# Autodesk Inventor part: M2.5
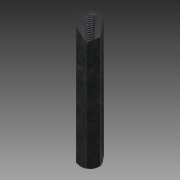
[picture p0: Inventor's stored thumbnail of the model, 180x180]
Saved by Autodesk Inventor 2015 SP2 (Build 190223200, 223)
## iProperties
Created: 2012-08
Part Number: M2.5
Material: Stahl
Document SubType Name: Modeling
Designer: rYan
Density: 7.85 g/cm^3
Mass: 3.36246 g
Surface Area: 5.74911 cm^2
Volume: 0.428339 cm^3
Appearance: Platte
Author: rYan
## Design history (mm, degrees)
derived "Abstandsbolzen Typ A.ipt"
feature "Volumenkörper1::Abstandsbolzen Typ A.ipt"
tag "Bezeichnung1"
node "Volumenkörper1"
other parameters: "SW" = 5, "L" = 35, "d2" = 0, "d16" = 45 deg
